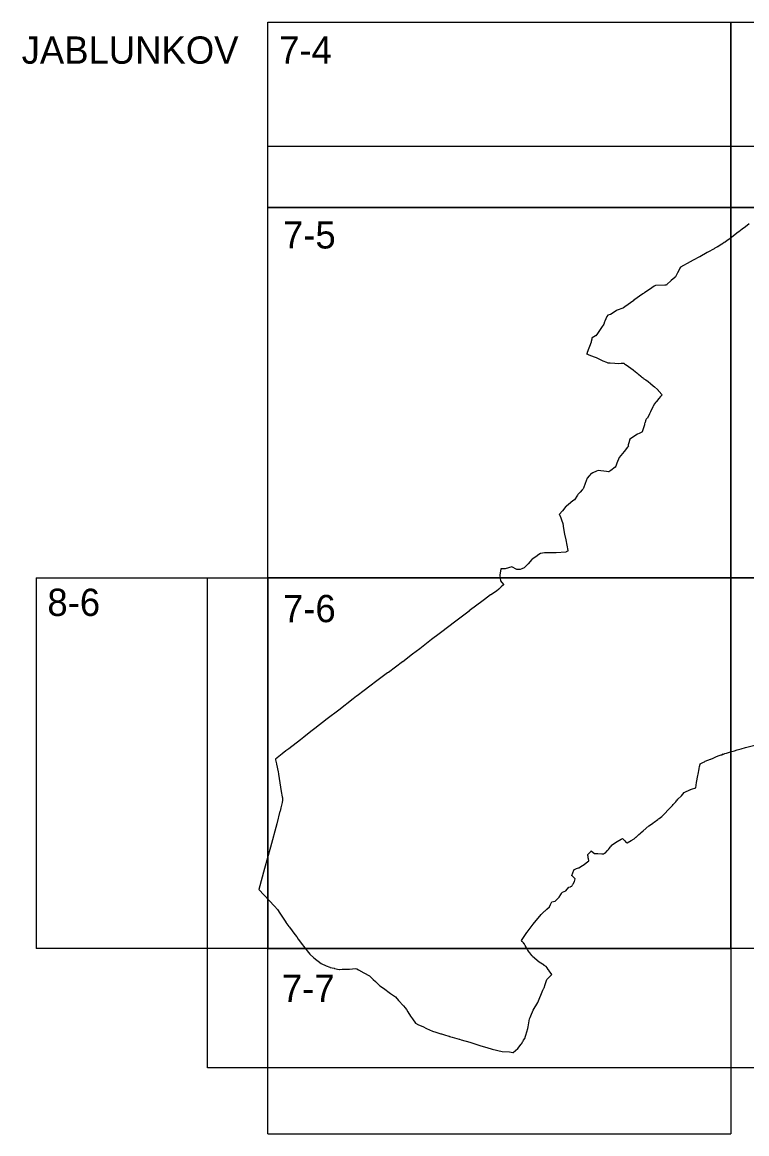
# Model space of a CAD drawing. Extents: x -449577 to -436680, y -1132317 to -1125726.
# Drawn here: x -444051.3 to -443806.9, y -1128344.4 to -1127969.4 of the extents above; entities that cross this region are included whole.
import ezdxf

# ---------------------------------------------------------------- set-up
doc = ezdxf.new("R2010")
doc.units = 0
for name, color, linetype in [('Vrstva 1', 7, 'Continuous'), ('Vrstva 10', 7, 'Continuous'), ('Vrstva 4', 7, 'Continuous')]:
    doc.layers.add(name, color=color, linetype=linetype)

msp = doc.modelspace()

# ---------------------------------------------------------------- linework, layer by layer
at = {"layer": 'Vrstva 1'}
for points in [[(-443806.12, -1128037.46), (-443807.33, -1128038.42), (-443807.33, -1128038.42), (-443808.48, -1128039.29), (-443809.05, -1128039.72), (-443809.63, -1128040.16), (-443809.79, -1128040.28), (-443811.92, -1128041.92), (-443812.99, -1128042.74), (-443813.46, -1128043.08), (-443814.22, -1128043.59), (-443814.47, -1128043.75), (-443815.06, -1128044.14), (-443815.1, -1128044.17), (-443815.31, -1128044.31), (-443816.22, -1128044.91), (-443816.23, -1128044.91), (-443816.7, -1128045.17), (-443816.85, -1128045.25), (-443817.03, -1128045.35), (-443817.49, -1128045.6), (-443817.67, -1128045.71), (-443817.83, -1128045.8), (-443817.93, -1128045.86), (-443818.17, -1128046), (-443819.83, -1128046.94), (-443820, -1128047.03), (-443820.23, -1128047.16), (-443822.7, -1128048.56), (-443822.82, -1128048.63), (-443824.93, -1128049.76), (-443825.95, -1128050.31), (-443829.29, -1128052.12), (-443829.46, -1128052.42), (-443829.52, -1128052.53), (-443830.3, -1128053.99), (-443830.98, -1128055.31), (-443831.12, -1128055.44), (-443831.21, -1128055.52), (-443832.35, -1128056.56), (-443833.86, -1128057.94), (-443834.03, -1128058.09), (-443834.03, -1128058.1), (-443834.5, -1128058.11), (-443837.69, -1128058.2), (-443837.7, -1128058.2), (-443838.13, -1128058.49), (-443838.96, -1128059.06), (-443841.43, -1128060.72), (-443841.47, -1128060.74), (-443841.71, -1128060.92), (-443841.98, -1128061.12), (-443844.96, -1128063.25), (-443845.03, -1128063.3), (-443848.03, -1128065.48), (-443848.5, -1128065.82), (-443848.66, -1128065.88), (-443850.6, -1128066.6), (-443850.61, -1128066.6), (-443851, -1128066.84), (-443852.88, -1128068), (-443853.8, -1128068.21), (-443854.05, -1128068.72), (-443854.81, -1128070.23), (-443854.82, -1128070.24), (-443854.89, -1128070.5), (-443855.09, -1128071.34), (-443855.92, -1128072.45), (-443857.29, -1128074.4), (-443857.85, -1128075.21), (-443857.88, -1128075.23), (-443859.04, -1128075.87), (-443859.14, -1128075.93), (-443859.21, -1128076.32), (-443859.36, -1128077.13), (-443859.41, -1128077.32), (-443860.7, -1128080.9), (-443860.87, -1128081.38), (-443860.84, -1128081.37), (-443860.82, -1128081.36), (-443860.14, -1128081.62), (-443858.33, -1128082.28), (-443857.71, -1128082.57), (-443855.42, -1128083.65), (-443855.4, -1128083.65), (-443854.24, -1128084.12), (-443853.77, -1128084.3), (-443853.74, -1128084.31), (-443853.31, -1128084.34), (-443853.17, -1128084.35), (-443852.95, -1128084.37), (-443851.35, -1128084.47), (-443850.31, -1128084.54), (-443849.26, -1128084.51), (-443848.42, -1128084.48), (-443848.41, -1128084.48), (-443848.13, -1128084.63), (-443847.76, -1128084.89), (-443847.21, -1128085.27), (-443846.82, -1128085.55), (-443845.26, -1128086.69), (-443845.09, -1128086.81), (-443843.98, -1128087.73), (-443843.59, -1128088.05), (-443843.41, -1128088.2), (-443842.66, -1128088.81), (-443842.39, -1128089.04), (-443841.79, -1128089.53), (-443841.57, -1128089.71), (-443840.93, -1128090.13), (-443840.18, -1128090.63), (-443840.15, -1128090.65), (-443839.39, -1128091.33), (-443838.51, -1128092.11), (-443838.07, -1128092.49), (-443837.06, -1128093.38), (-443836.8, -1128093.61), (-443836.75, -1128093.66), (-443836.65, -1128093.76), (-443836.64, -1128093.77), (-443836.55, -1128093.87), (-443836.52, -1128093.9), (-443835.47, -1128095.13), (-443835.48, -1128095.14), (-443835.92, -1128095.63), (-443835.98, -1128095.7), (-443836.55, -1128096.33), (-443837.37, -1128097.39), (-443837.54, -1128097.6), (-443838.1, -1128098.32), (-443838.4, -1128098.85), (-443838.42, -1128098.89), (-443838.43, -1128098.91), (-443838.56, -1128099.19), (-443839.36, -1128100.86), (-443839.67, -1128101.5), (-443840.29, -1128102.79), (-443840.4, -1128103.03), (-443840.41, -1128103.03), (-443840.45, -1128103.06), (-443840.74, -1128103.26), (-443840.82, -1128103.3), (-443840.87, -1128103.4), (-443840.96, -1128103.6), (-443841.05, -1128103.88), (-443841.22, -1128104.44), (-443841.23, -1128104.46), (-443841.35, -1128104.96), (-443841.37, -1128105.03), (-443841.36, -1128105.09), (-443841.35, -1128105.17), (-443841.35, -1128105.24), (-443841.36, -1128105.29), (-443842.24, -1128107.62), (-443842.26, -1128107.67), (-443842.28, -1128107.71), (-443842.29, -1128107.72), (-443842.99, -1128108.02), (-443843.24, -1128108.13), (-443843.71, -1128108.37), (-443846.32, -1128110.06), (-443846.32, -1128110.06), (-443846.69, -1128111.37), (-443846.77, -1128111.63), (-443846.88, -1128112.05), (-443846.94, -1128112.26), (-443846.94, -1128112.27), (-443846.93, -1128112.27), (-443846.76, -1128112.43), (-443846.77, -1128112.44), (-443847.13, -1128112.83), (-443847.93, -1128113.83), (-443847.94, -1128113.84), (-443848.15, -1128114.09), (-443848.15, -1128114.1), (-443848.27, -1128114.25), (-443849.43, -1128115.6), (-443849.97, -1128116.23), (-443850.73, -1128118.18), (-443851.11, -1128119.2), (-443851.24, -1128119.55), (-443852.77, -1128120.65), (-443853.39, -1128121.09), (-443853.57, -1128121.13), (-443853.59, -1128121.13), (-443854.22, -1128121.04), (-443857.06, -1128120.62), (-443857.55, -1128120.86), (-443858.88, -1128121.5), (-443859.42, -1128121.76), (-443859.45, -1128121.79), (-443859.88, -1128122.2), (-443860.05, -1128122.42), (-443860.71, -1128123.27), (-443860.71, -1128123.28), (-443861.38, -1128125.08), (-443861.95, -1128126.58), (-443861.95, -1128126.58), (-443862.09, -1128126.8), (-443862.42, -1128127.17), (-443863.14, -1128127.97), (-443863.84, -1128128.74), (-443863.85, -1128128.76), (-443863.98, -1128128.95), (-443865.05, -1128130.52), (-443865.52, -1128130.9), (-443867.09, -1128132.16), (-443867.76, -1128132.7), (-443867.86, -1128132.78), (-443867.89, -1128132.82), (-443869.01, -1128134.25), (-443870.15, -1128135.56), (-443870, -1128135.73), (-443869.99, -1128135.76), (-443869.99, -1128135.77), (-443868.98, -1128138.53), (-443868.7, -1128140.19), (-443868.38, -1128142.14), (-443867.97, -1128144.1), (-443867.24, -1128147.6), (-443867.2, -1128147.8), (-443867.85, -1128148.14), (-443867.97, -1128148.21), (-443871.14, -1128148.47), (-443871.3, -1128148.47), (-443872.79, -1128148.44), (-443875.18, -1128148.42), (-443876.46, -1128148.69), (-443877.06, -1128148.96), (-443878.04, -1128149.76), (-443879.34, -1128150.63), (-443879.43, -1128150.74), (-443880.59, -1128152.16), (-443882.04, -1128153.5), (-443882.73, -1128153.82), (-443883.33, -1128154.1), (-443884.5, -1128154.03), (-443886.11, -1128153.18), (-443888.35, -1128153.85), (-443889.83, -1128153.82), (-443890.21, -1128155.93), (-443890.22, -1128155.95), (-443890.23, -1128156.04), (-443889.94, -1128157.85), (-443888.97, -1128159.17), (-443888.96, -1128159.19), (-443889.7, -1128159.94), (-443890.31, -1128160.5), (-443890.56, -1128160.73), (-443891.36, -1128161.36), (-443893.29, -1128162.59), (-443893.35, -1128162.63), (-443895.32, -1128164.16), (-443895.38, -1128164.2), (-443895.87, -1128164.58), (-443900.53, -1128168.04), (-443900.56, -1128168.07), (-443905.51, -1128171.83), (-443909.77, -1128175.08), (-443910.65, -1128175.74), (-443913.22, -1128177.68), (-443917.22, -1128180.81), (-443919.66, -1128182.68), (-443922.97, -1128185.21), (-443923.02, -1128185.25), (-443927.81, -1128188.76), (-443928.04, -1128188.94), (-443931.65, -1128191.62), (-443934.04, -1128193.44), (-443936.01, -1128194.92), (-443938.33, -1128196.67), (-443938.56, -1128196.84), (-443939.69, -1128197.73), (-443944.51, -1128201.53), (-443948.4, -1128204.48), (-443952.62, -1128207.73), (-443953.91, -1128208.73), (-443956.3, -1128210.61), (-443957.48, -1128211.53), (-443961.42, -1128214.58), (-443962.35, -1128215.29), (-443963.59, -1128216.25), (-443965.91, -1128218.05), (-443965.91, -1128218.05), (-443965.87, -1128218.23), (-443965.58, -1128219.61), (-443965.55, -1128219.77), (-443965.02, -1128222.31), (-443964.86, -1128223.04), (-443964.86, -1128223.08), (-443963.93, -1128228.96), (-443963.92, -1128228.99), (-443963.62, -1128230.72), (-443963.62, -1128230.74), (-443963.56, -1128231.11), (-443963.5, -1128231.53), (-443963.53, -1128231.9), (-443963.68, -1128232.63), (-443964.06, -1128234.42), (-443964.35, -1128235.6), (-443964.37, -1128235.65), (-443965.48, -1128239.82), (-443967.58, -1128247.7), (-443969.57, -1128254.92), (-443971.5, -1128262.02), (-443971.51, -1128262.06), (-443966.23, -1128267.66), (-443965.18, -1128268.79), (-443964.42, -1128270.01), (-443962.4, -1128273.07), (-443962.35, -1128273.14), (-443961.34, -1128274.55), (-443961.18, -1128274.76), (-443959.3, -1128277.24), (-443958.73, -1128277.98), (-443958.7, -1128278.02), (-443958.18, -1128278.74), (-443956.8, -1128280.64), (-443956.47, -1128281.09), (-443954.32, -1128283.81), (-443952.92, -1128285.03), (-443950.52, -1128287.01), (-443948.78, -1128287.76), (-443947.59, -1128288.28), (-443947.46, -1128288.33), (-443946.13, -1128288.61), (-443945.99, -1128288.64), (-443944.37, -1128288.97), (-443944.34, -1128288.97), (-443943.38, -1128288.95), (-443943, -1128288.95), (-443942.48, -1128288.94), (-443941.8, -1128288.93), (-443940.89, -1128288.89), (-443938.94, -1128288.73), (-443938.49, -1128288.8), (-443937.83, -1128289.15), (-443936.11, -1128290.1), (-443934.15, -1128291.2), (-443933.63, -1128291.68), (-443932.91, -1128292.36), (-443932.11, -1128293.11), (-443930.79, -1128294.41), (-443930.65, -1128294.51), (-443929.46, -1128295.36), (-443927.05, -1128297.07), (-443925.41, -1128298.25), (-443924.36, -1128299.43), (-443922.72, -1128301.25), (-443922.08, -1128301.96), (-443921.72, -1128302.55), (-443921.26, -1128303.29), (-443920.32, -1128304.76), (-443919.69, -1128305.68), (-443918.65, -1128307.12), (-443917.58, -1128307.63), (-443916.2, -1128308.28), (-443914.89, -1128308.89), (-443912.92, -1128309.78), (-443911.79, -1128310.13), (-443910.07, -1128310.7), (-443909.92, -1128310.75), (-443908.83, -1128311.07), (-443907.41, -1128311.49), (-443907.4, -1128311.49), (-443907.19, -1128311.55), (-443907.13, -1128311.57), (-443906.27, -1128311.83), (-443903.88, -1128312.52), (-443903.76, -1128312.56), (-443903.28, -1128312.7), (-443900.35, -1128313.57), (-443897.66, -1128314.4), (-443897.32, -1128314.5), (-443896.56, -1128314.73), (-443894.55, -1128315.35), (-443892.82, -1128315.9), (-443889.36, -1128316.64)], [(-443889.36, -1128316.64), (-443886.97, -1128316.83), (-443885.77, -1128317.06), (-443885.66, -1128316.97), (-443884.08, -1128315.7), (-443883.05, -1128314.22), (-443882.94, -1128314.07), (-443882.42, -1128313.31), (-443882.31, -1128313.14), (-443882.17, -1128312.91), (-443881.79, -1128312.28), (-443881.52, -1128311.45), (-443881.5, -1128311.38), (-443881.48, -1128311.33), (-443881.45, -1128311.22), (-443881.42, -1128311.13), (-443881.42, -1128311.12), (-443880.79, -1128308.92), (-443880.65, -1128308.4), (-443880.2, -1128305.65), (-443880.2, -1128305.65), (-443880.01, -1128305.21), (-443879.75, -1128304.59), (-443878.96, -1128302.76), (-443877.39, -1128300.11), (-443875.64, -1128295.98), (-443875.32, -1128295.34), (-443875.28, -1128295.21), (-443874.89, -1128294.11), (-443874.3, -1128292.44), (-443872.62, -1128290.73), (-443873.55, -1128289.49), (-443873.61, -1128289.4), (-443873.66, -1128289.34), (-443873.69, -1128289.3), (-443873.76, -1128289.2), (-443873.81, -1128289.12), (-443873.89, -1128289), (-443874.25, -1128288.48), (-443874.62, -1128288.02), (-443875.19, -1128287.65), (-443875.29, -1128287.59), (-443876.94, -1128286.52), (-443879.13, -1128284.58), (-443879.26, -1128284.41), (-443879.29, -1128284.37), (-443879.37, -1128284.27), (-443879.71, -1128283.85), (-443880.04, -1128283.44), (-443880.3, -1128283.12), (-443880.78, -1128282.53), (-443880.86, -1128282.43), (-443881.36, -1128281.47), (-443881.65, -1128280.91), (-443881.88, -1128280.48), (-443881.93, -1128280.39), (-443881.97, -1128280.34), (-443882.23, -1128280.05), (-443882.43, -1128279.82), (-443882.69, -1128279.53), (-443882.91, -1128279.28), (-443881.05, -1128276.54), (-443880.96, -1128276.42), (-443880.64, -1128275.97), (-443880.32, -1128275.53), (-443878.99, -1128273.7), (-443876.31, -1128270.44), (-443875.96, -1128270.12), (-443875.25, -1128269.42), (-443875.14, -1128269.33), (-443874.95, -1128269.19), (-443874.35, -1128268.71), (-443873.49, -1128267.87), (-443873.08, -1128267.11), (-443872.61, -1128266.24), (-443871.56, -1128266), (-443870.16, -1128264.57), (-443869.62, -1128263.72), (-443869.61, -1128263.71), (-443869.61, -1128263.69), (-443869.4, -1128263.36), (-443869.35, -1128263.28), (-443869.11, -1128262.89), (-443867.95, -1128262.45), (-443866.93, -1128261.27), (-443866.4, -1128261.07), (-443866.28, -1128261.02), (-443865.86, -1128260.86), (-443865.64, -1128260.47), (-443865.59, -1128260.38), (-443865.42, -1128260.08), (-443865.01, -1128259.34), (-443864.81, -1128258.43), (-443864.81, -1128258.41), (-443864.8, -1128258.4), (-443865.85, -1128257.41), (-443865.87, -1128257.4), (-443865.88, -1128257.38), (-443865.93, -1128257.34), (-443865.28, -1128255.54), (-443865.21, -1128255.34), (-443865.05, -1128255.28), (-443864.32, -1128254.99), (-443863.63, -1128254.72), (-443863.51, -1128254.67), (-443862.3, -1128253.96), (-443862.18, -1128253.88), (-443862.18, -1128253.88), (-443862.17, -1128253.87), (-443862.05, -1128253.8), (-443860.19, -1128252.4), (-443860.19, -1128252.36), (-443860.22, -1128252.2), (-443860.29, -1128251.72), (-443860.35, -1128251.37), (-443860.45, -1128250.75), (-443860.47, -1128250.64), (-443860.49, -1128250.51), (-443860.51, -1128250.34), (-443860.54, -1128250.2), (-443860, -1128249.64), (-443859.44, -1128249.07), (-443859.4, -1128249.02), (-443859.26, -1128249.12), (-443858.26, -1128249.91), (-443857.58, -1128249.92), (-443857.52, -1128249.92), (-443857.27, -1128249.93), (-443857.11, -1128249.93), (-443855.8, -1128249.95), (-443855.17, -1128249.97), (-443854.9, -1128249.81), (-443854.87, -1128249.79), (-443854.75, -1128249.72), (-443854.61, -1128249.63), (-443854.57, -1128249.6), (-443854.03, -1128249), (-443853.92, -1128248.88), (-443853.83, -1128248.78), (-443853.66, -1128248.6), (-443853.58, -1128248.51), (-443853.47, -1128248.39), (-443853.44, -1128248.35), (-443853.41, -1128248.32), (-443853.36, -1128248.26), (-443853.27, -1128248.15), (-443852.87, -1128247.65), (-443852.66, -1128247.39), (-443852.41, -1128247.07), (-443852.3, -1128246.99), (-443850.84, -1128245.92), (-443850.63, -1128245.79), (-443849.27, -1128245.02), (-443848.87, -1128244.79), (-443848.87, -1128244.79), (-443848.73, -1128244.94), (-443848.02, -1128245.65), (-443847.65, -1128246.03), (-443847.47, -1128246.2), (-443847.32, -1128246.35), (-443847.23, -1128246.31), (-443845.95, -1128245.54), (-443845.86, -1128245.49), (-443844.93, -1128244.93), (-443844.89, -1128244.9), (-443844.56, -1128244.61), (-443844.51, -1128244.57), (-443844.34, -1128244.42), (-443844.33, -1128244.41), (-443844.33, -1128244.41), (-443844.29, -1128244.37), (-443844.25, -1128244.33), (-443843.36, -1128243.52), (-443843.34, -1128243.51), (-443842.75, -1128242.97), (-443842.64, -1128242.88), (-443842.53, -1128242.78), (-443842.53, -1128242.78), (-443842.52, -1128242.78), (-443842.52, -1128242.78), (-443842.52, -1128242.77), (-443842.51, -1128242.77), (-443842.5, -1128242.76), (-443842.5, -1128242.76), (-443842.49, -1128242.75), (-443842.49, -1128242.75), (-443842.48, -1128242.75), (-443842.48, -1128242.75), (-443841.9, -1128242.26), (-443839.91, -1128240.58), (-443838.71, -1128239.73), (-443838.59, -1128239.65), (-443838.54, -1128239.61), (-443838.52, -1128239.6), (-443838.47, -1128239.57), (-443838.11, -1128239.3), (-443836.87, -1128238.36), (-443836.69, -1128238.22), (-443836.48, -1128238.06), (-443836.46, -1128238.04), (-443835.58, -1128237.37), (-443835.23, -1128237.1), (-443835.18, -1128237.04), (-443835.09, -1128236.94), (-443834.45, -1128236.26), (-443833.55, -1128235.28), (-443832.19, -1128233.87), (-443831.97, -1128233.64), (-443831.72, -1128233.36), (-443830.88, -1128232.41), (-443830.59, -1128232.09), (-443830.39, -1128231.88), (-443830.1, -1128231.56), (-443828.92, -1128230.37), (-443827.99, -1128229.35), (-443825.93, -1128228.34), (-443825.77, -1128228.29), (-443825.57, -1128228.21), (-443824.13, -1128227.72), (-443823.98, -1128226.85), (-443823.82, -1128225.98), (-443823.4, -1128223.61), (-443823.32, -1128223.14), (-443822.99, -1128221.26), (-443822.79, -1128220.38), (-443822.76, -1128220.26), (-443822.71, -1128220.07), (-443822.7, -1128220.03), (-443822.68, -1128219.96), (-443822.67, -1128219.92), (-443822.66, -1128219.87), (-443822.65, -1128219.83), (-443822.64, -1128219.81), (-443822.58, -1128219.6), (-443821.5, -1128219.06), (-443821.21, -1128218.92), (-443821.19, -1128218.91), (-443820.94, -1128218.78), (-443820.89, -1128218.76), (-443819.12, -1128218.04), (-443819.09, -1128218.03), (-443819.06, -1128218.01), (-443818.26, -1128217.7), (-443817.3, -1128217.3), (-443816.49, -1128216.96), (-443815.55, -1128216.57), (-443815.47, -1128216.54), (-443814.86, -1128216.3), (-443815.01, -1128216.46), (-443814.77, -1128216.37), (-443814.28, -1128216.17), (-443813.75, -1128216.01), (-443812.05, -1128215.49), (-443811.46, -1128215.32), (-443811.01, -1128215.2), (-443810.12, -1128214.95), (-443808.81, -1128214.57), (-443807.27, -1128214.11), (-443803.73, -1128213.24)]]:
    msp.add_lwpolyline(points, dxfattribs=at)
at = {"layer": 'Vrstva 10'}
msp.add_lwpolyline([(-443655.97, -1128011.25), (-443655.97, -1128322.23), (-443988.84, -1128322.23), (-443988.84, -1128156.93), (-443968.47, -1128156.93), (-443968.47, -1128031.93), (-443968.47, -1128011.25), (-443655.97, -1128011.25)], dxfattribs=at)
at = {"layer": 'Vrstva 4'}
for p, q in [((-443968.47, -1127969.43), (-443655.97, -1127969.43)), ((-444046.6, -1128156.93), (-444046.6, -1128281.93)), ((-443968.47, -1128344.43), (-443812.22, -1128344.43))]:
    msp.add_line(p, q, dxfattribs=at)
for points in [[(-443812.22, -1127969.43), (-443812.22, -1128031.93), (-443968.47, -1128031.93), (-443968.47, -1127969.43)], [(-443655.97, -1127969.43), (-443655.97, -1128031.93), (-443812.22, -1128031.93), (-443812.22, -1127969.43)], [(-444046.6, -1128156.93), (-443968.47, -1128156.93), (-443968.47, -1128281.93), (-444046.6, -1128281.93)], [(-443968.47, -1128344.43), (-443968.47, -1128281.93), (-443812.22, -1128281.93), (-443812.22, -1128344.43)]]:
    msp.add_lwpolyline(points, dxfattribs=at)
for points in [[(-443812.22, -1128031.93), (-443812.22, -1128156.93), (-443968.47, -1128156.93), (-443968.47, -1128031.93)], [(-443655.97, -1128031.93), (-443655.97, -1128156.93), (-443812.22, -1128156.93), (-443812.22, -1128031.93)], [(-443812.22, -1128156.93), (-443812.22, -1128281.93), (-443968.47, -1128281.93), (-443968.47, -1128156.93)], [(-443655.97, -1128156.93), (-443655.97, -1128281.93), (-443812.22, -1128281.93), (-443812.22, -1128156.93)]]:
    msp.add_lwpolyline(points, close=True, dxfattribs=at)

# ---------------------------------------------------------------- texts
at = {"layer": 'Vrstva 1'}
for s, p in [('JABLUNKOV', (-444051.51, -1127983.43)), ('7-4', (-443964.66, -1127983.43)), ('7-5', (-443963.35, -1128045.77)), ('8-6', (-444042.82, -1128169.74)), ('7-6', (-443963.35, -1128171.84)), ('7-7', (-443963.71, -1128300.01))]:
    msp.add_text(s, height=9.2, dxfattribs=at).set_placement(p)

doc.saveas('drawing.dxf')
